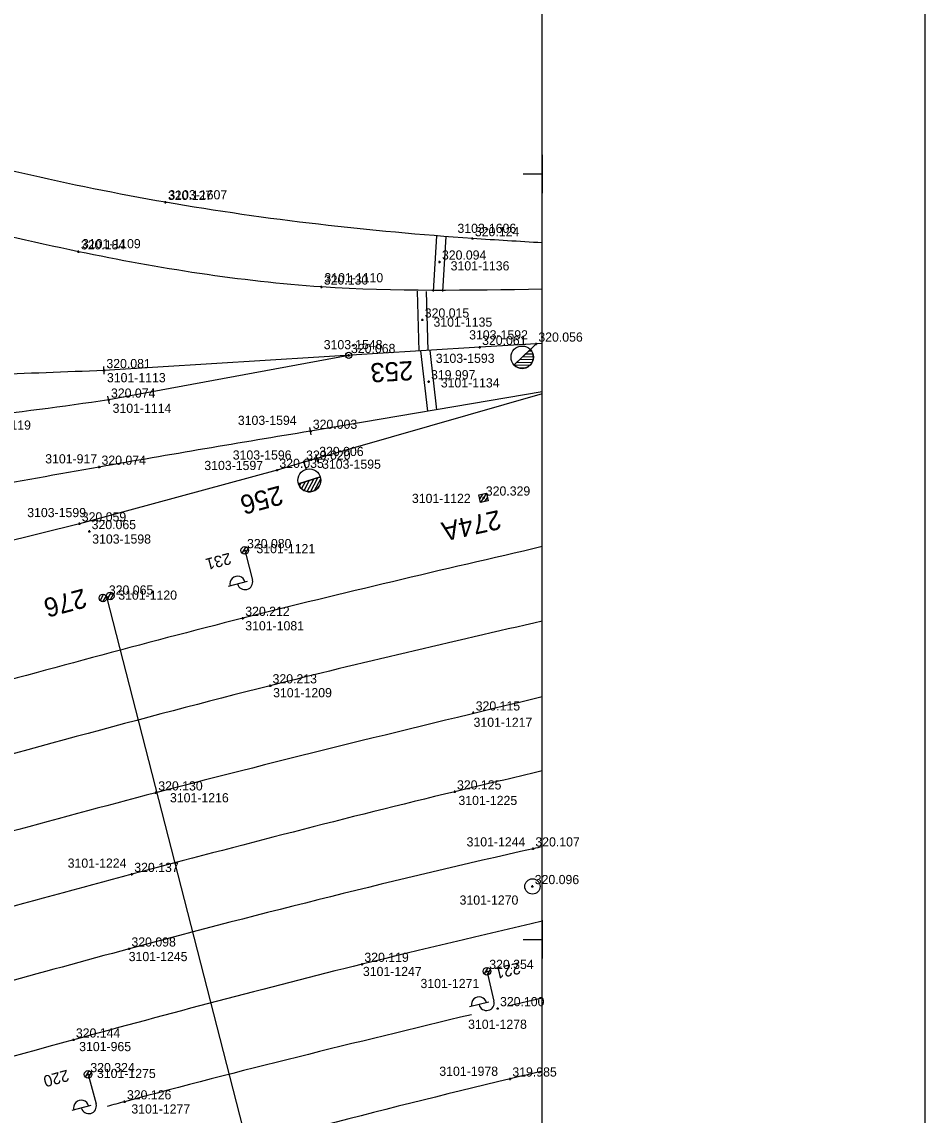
# Model space of a CAD drawing. Extents: x -821875 to -821475, y -1070280 to -1069975.
# Drawn here: x -821534 to -821475, y -1070161.5 to -1070090.1 of the extents above; entities that cross this region are included whole.
import ezdxf

# ---------------------------------------------------------------- set-up
doc = ezdxf.new("R2010")
doc.units = 0
for name, color, linetype in [('Vrstva 1', 7, 'Continuous'), ('Vrstva 11', 7, 'Continuous'), ('Vrstva 2', 7, 'Continuous'), ('Vrstva 25', 7, 'Continuous'), ('Vrstva 3', 7, 'Continuous'), ('Vrstva 43', 7, 'Continuous'), ('Vrstva 60', 7, 'Continuous'), ('Vrstva 61', 7, 'Continuous'), ('Vrstva 7', 7, 'Continuous')]:
    doc.layers.add(name, color=color, linetype=linetype)

# ---------------------------------------------------------------- blocks, each defined once
blk = doc.blocks.new('BOD')
at = {"layer": 'Vrstva 3'}
for p, q in [((-0.15, 0), (0.15, 0)), ((0, -0.15), (0, 0.15))]:
    blk.add_line(p, q, dxfattribs=at)

msp = doc.modelspace()

# ---------------------------------------------------------------- linework, layer by layer
at = {"layer": 'Vrstva 1'}
msp.add_line((-821500, -1070153.839), (-821502.241, -1070154.359), dxfattribs=at)
for points in [[(-821475, -1069975), (-821875, -1069975), (-821875, -1070275), (-821475, -1070275)], [(-821500, -1070000), (-821850, -1070000), (-821850, -1070250), (-821500, -1070250)], [(-821500, -1070000), (-821850, -1070000), (-821850, -1070250), (-821500, -1070250)]]:
    msp.add_lwpolyline(points, close=True, dxfattribs=at)
for points in [[(-821500, -1070100), (-821500, -1070098.75), (-821500, -1070100)], [(-821501.25, -1070100), (-821500, -1070100)], [(-821500, -1070100), (-821500, -1070101.25)], [(-821500, -1070111.081), (-821500.408, -1070111.107)], [(-821514.719, -1070118.578), (-821515.574, -1070118.819)], [(-821500, -1070150), (-821500, -1070148.75), (-821500, -1070150)], [(-821501.25, -1070150), (-821500, -1070150)], [(-821500, -1070150), (-821500, -1070151.25)]]:
    msp.add_lwpolyline(points, dxfattribs=at)
for points in [[(-821500, -1070107.532), (-821514.414, -1070107.377), (-821530.282, -1070105.08), (-821548.548, -1070100.3), (-821566.929, -1070093.631), (-821576.512, -1070089.417), (-821586.373, -1070084.578)], [(-821500, -1070104.505), (-821504.552, -1070104.218), (-821524.6, -1070101.851), (-821543.27, -1070097.565), (-821559.418, -1070092.193), (-821575.427, -1070085.277)], [(-821528.616, -1070112.837), (-821543.775, -1070113.227), (-821563.491, -1070112.067), (-821572.815, -1070110.801), (-821588.592, -1070107.193), (-821603.911, -1070102.306)], [(-821528.316, -1070114.765), (-821537.381, -1070115.9), (-821550.005, -1070116.34), (-821563.928, -1070115.755), (-821574.13, -1070114.598), (-821590.666, -1070111.251), (-821610.167, -1070105.183)], [(-821515.135, -1070116.801), (-821528.933, -1070119.148), (-821545.007, -1070122.191), (-821565.452, -1070126.847), (-821593.911, -1070134.524), (-821616.729, -1070140.773), (-821646.681, -1070148.977), (-821681.98, -1070158.691), (-821694.065, -1070162.076), (-821706.535, -1070165.88), (-821718.507, -1070169.937)], [(-821500, -1070124.347), (-821519.547, -1070129.021), (-821539.192, -1070134.264), (-821572.805, -1070143.407)], [(-821500, -1070129.211), (-821517.764, -1070133.43), (-821543.081, -1070140.233), (-821582.867, -1070151.05), (-821612.032, -1070158.997), (-821647.71, -1070168.745)], [(-821500, -1070134.157), (-821525.227, -1070140.424), (-821545.665, -1070145.962), (-821584.89, -1070156.649), (-821608.863, -1070163.173), (-821645.742, -1070173.228), (-821684.141, -1070183.689)], [(-821500, -1070139.002), (-821505.719, -1070140.359), (-821526.796, -1070145.75), (-821547.362, -1070151.333), (-821583.687, -1070161.245), (-821611.332, -1070168.765), (-821648.899, -1070179.006), (-821680.4, -1070187.609), (-821711.133, -1070195.974)], [(-821500, -1070143.947), (-821500.602, -1070144.082), (-821526.98, -1070150.62), (-821544.477, -1070155.432), (-821558.026, -1070159.151), (-821579.135, -1070164.951), (-821610.376, -1070173.463), (-821647.463, -1070183.595), (-821678.921, -1070192.191), (-821710.276, -1070200.761)], [(-821500, -1070148.817), (-821511.77, -1070151.622), (-821530.609, -1070156.564), (-821556.604, -1070163.701), (-821576.895, -1070169.217), (-821607.294, -1070177.525), (-821643.435, -1070187.343), (-821669.656, -1070194.488)], [(-821504.632, -1070154.921), (-821527.273, -1070160.604), (-821528.405, -1070160.911)], [(-821500, -1070158.612), (-821502.104, -1070159.113), (-821527.988, -1070165.772), (-821558.427, -1070174.094), (-821579.522, -1070179.891)]]:
    msp.add_spline(points, degree=3, dxfattribs=at)
at = {"layer": 'Vrstva 11'}
for p, q in [((-821503.904, -1070120.919), (-821504.084, -1070121.201)), ((-821503.646, -1070120.863), (-821504.026, -1070121.458)), ((-821503.589, -1070121.122), (-821503.767, -1070121.401)), ((-821528.644, -1070127.452), (-821528.881, -1070127.861)), ((-821528.488, -1070127.557), (-821528.713, -1070127.944)), ((-821528.453, -1070127.631), (-821517.074, -1070171.964)), ((-821528.158, -1070127.324), (-821528.396, -1070127.734)), ((-821528.003, -1070127.429), (-821528.227, -1070127.816))]:
    msp.add_line(p, q, dxfattribs=at)
msp.add_lwpolyline([(-821503.539, -1070121.35), (-821504.027, -1070121.458), (-821504.135, -1070120.97), (-821503.647, -1070120.862)], close=True, dxfattribs=at)
msp.add_lwpolyline([(-821503.539, -1070121.35), (-821504.027, -1070121.458), (-821504.135, -1070120.97), (-821503.647, -1070120.862), (-821503.539, -1070121.35)], dxfattribs=at)
for centre in [(-821528.695, -1070127.695), (-821528.695, -1070127.695), (-821528.211, -1070127.567), (-821528.211, -1070127.567)]:
    msp.add_circle(centre, 0.25, dxfattribs=at)
at = {"layer": 'Vrstva 2'}
for p, q in [((-821501.837, -1070112.48), (-821500.782, -1070111.467)), ((-821501.834, -1070112.478), (-821500.778, -1070111.464)), ((-821500.777, -1070111.464), (-821500.408, -1070111.107)), ((-821500.6, -1070112.149), (-821501.474, -1070112.131)), ((-821500.58, -1070111.965), (-821501.285, -1070111.95)), ((-821500.606, -1070111.779), (-821501.097, -1070111.769)), ((-821500.687, -1070111.592), (-821500.908, -1070111.588)), ((-821528.6, -1070113.087), (-821528.632, -1070112.587)), ((-821501.837, -1070112.481), (-821501.837, -1070112.48)), ((-821500.819, -1070112.514), (-821501.823, -1070112.494)), ((-821500.672, -1070112.332), (-821501.663, -1070112.312)), ((-821501.178, -1070112.692), (-821501.474, -1070112.686)), ((-821528.271, -1070115.011), (-821528.361, -1070114.519)), ((-821515.093, -1070117.048), (-821515.177, -1070116.554)), ((-821514.65, -1070118.819), (-821514.788, -1070118.337)), ((-821515.574, -1070118.819), (-821515.428, -1070119.297)), ((-821514.492, -1070119.796), (-821515.927, -1070120.234)), ((-821515.927, -1070120.234), (-821514.492, -1070119.796)), ((-821515.553, -1070120.68), (-821515.197, -1070120.011)), ((-821515.362, -1070120.747), (-821514.926, -1070119.928)), ((-821515.142, -1070120.76), (-821514.656, -1070119.846)), ((-821514.876, -1070120.686), (-821514.467, -1070119.918)), ((-821515.854, -1070120.394), (-821515.738, -1070120.176)), ((-821515.718, -1070120.564), (-821515.467, -1070120.094))]:
    msp.add_line(p, q, dxfattribs=at)
for points in [[(-821500.408, -1070111.107), (-821504.082, -1070111.324), (-821528.616, -1070112.837)], [(-821512.643, -1070111.852), (-821528.316, -1070114.765)], [(-821500, -1070114.227), (-821515.135, -1070116.801)], [(-821500, -1070114.359), (-821514.719, -1070118.578)], [(-821517.318, -1070119.351), (-821530.222, -1070122.85), (-821540.596, -1070125.428)], [(-821515.574, -1070118.819), (-821517.318, -1070119.351)]]:
    msp.add_lwpolyline(points, dxfattribs=at)
for centre, radius in [((-821501.309, -1070111.973), 0.731), ((-821512.643, -1070111.852), 0.2), ((-821515.209, -1070120.015), 0.75)]:
    msp.add_circle(centre, radius, dxfattribs=at)
for centre, radius, start, end in [((-821501.31, -1070111.974), 0.732, 223.85996, 43.82081), ((-821515.209, -1070120.015), 0.75, 196.95416, 16.95416)]:
    msp.add_arc(centre, radius, start, end, dxfattribs=at)
at = {"layer": 'Vrstva 25'}
for p, q in [((-821519.37, -1070124.354), (-821519.613, -1070124.768)), ((-821519.218, -1070124.465), (-821519.441, -1070124.845)), ((-821519.368, -1070124.838), (-821518.926, -1070126.531)), ((-821519.264, -1070126.62), (-821520.523, -1070126.948)), ((-821503.546, -1070151.845), (-821503.799, -1070152.252)), ((-821503.397, -1070151.959), (-821503.629, -1070152.333)), ((-821503.556, -1070152.329), (-821503.155, -1070154.032)), ((-821503.496, -1070154.112), (-821504.762, -1070154.41)), ((-821529.605, -1070158.583), (-821529.842, -1070158.998)), ((-821529.452, -1070158.692), (-821529.67, -1070159.073)), ((-821529.597, -1070159.066), (-821529.137, -1070160.754)), ((-821529.474, -1070160.846), (-821530.728, -1070161.189))]:
    msp.add_line(p, q, dxfattribs=at)
for centre in [(-821519.431, -1070124.596), (-821519.431, -1070124.596), (-821503.613, -1070152.085), (-821503.613, -1070152.085), (-821529.663, -1070158.825), (-821529.663, -1070158.825)]:
    msp.add_circle(centre, 0.25, dxfattribs=at)
for centre, start, end in [((-821519.895, -1070126.778), 13.92586, 195.33101), ((-821519.41, -1070126.657), 194.62844, 14.62844), ((-821504.131, -1070154.255), 12.51674, 193.92189), ((-821503.642, -1070154.146), 193.21932, 13.21932), ((-821530.103, -1070161.012), 14.56134, 195.96648), ((-821529.619, -1070160.886), 195.26391, 15.26391)]:
    msp.add_arc(centre, 0.5, start, end, dxfattribs=at)
at = {"layer": 'Vrstva 43'}
msp.add_circle((-821500.642, -1070146.543), 0.5, dxfattribs=at)
at = {"layer": 'Vrstva 7'}
for p, q in [((-821506.898, -1070104.051), (-821507.124, -1070107.68)), ((-821506.3, -1070104.097), (-821506.524, -1070107.687)), ((-821508.176, -1070107.66), (-821508.069, -1070111.57)), ((-821507.576, -1070107.672), (-821507.47, -1070111.533)), ((-821507.951, -1070111.563), (-821507.496, -1070115.502)), ((-821507.351, -1070111.526), (-821506.903, -1070115.401))]:
    msp.add_line(p, q, dxfattribs=at)

# ---------------------------------------------------------------- block references
at = {"layer": 'Vrstva 60', "xscale": 0.5, "yscale": 0.5}
for p in [(-821524.6, -1070101.851), (-821504.552, -1070104.218), (-821530.282, -1070105.08), (-821506.703, -1070105.746), (-821514.414, -1070107.377), (-821507.825, -1070109.53), (-821504.082, -1070111.324), (-821500.408, -1070111.107), (-821512.643, -1070111.852), (-821528.616, -1070112.837), (-821507.417, -1070113.568), (-821528.316, -1070114.765), (-821515.135, -1070116.801), (-821514.719, -1070118.578), (-821528.933, -1070119.148), (-821517.318, -1070119.351), (-821515.574, -1070118.819), (-821503.837, -1070121.16), (-821530.222, -1070122.85), (-821529.578, -1070123.354), (-821519.431, -1070124.596), (-821528.453, -1070127.631), (-821519.547, -1070129.021), (-821517.764, -1070133.43), (-821504.499, -1070135.2), (-821525.227, -1070140.424), (-821505.719, -1070140.359), (-821500.602, -1070144.082), (-821526.796, -1070145.75), (-821500.642, -1070146.543), (-821526.98, -1070150.62), (-821511.77, -1070151.622), (-821503.613, -1070152.085), (-821502.91, -1070154.516), (-821530.609, -1070156.564), (-821529.663, -1070158.825), (-821502.104, -1070159.113), (-821527.273, -1070160.604)]:
    msp.add_blockref('BOD', p, dxfattribs=at)

# ---------------------------------------------------------------- texts
at = {"layer": 'Vrstva 11'}
for s, rotation, p in [('274A', 192.48141, (-821502.855, -1070121.945)), ('276', 194.88708, (-821529.958, -1070127.07))]:
    msp.add_text(s, height=1.25, rotation=rotation, dxfattribs=at).set_placement(p)
at = {"layer": 'Vrstva 2'}
for s, rotation, p in [('253', 183.38017, (-821508.468, -1070112.213)), ('256', 195.1713, (-821517.135, -1070120.338))]:
    msp.add_text(s, height=1.25, rotation=rotation, dxfattribs=at).set_placement(p)
at = {"layer": 'Vrstva 25'}
for s, rotation, p in [('231', 194.62854, (-821520.428, -1070124.736)), ('221', 193.21919, (-821501.52, -1070151.492)), ('220', 195.26401, (-821531.028, -1070158.504))]:
    msp.add_text(s, height=0.75, rotation=rotation, dxfattribs=at).set_placement(p)
at = {"layer": 'Vrstva 60'}
for s, p in [('3103-1607', (-821524.414, -1070101.661)), ('3103-1606', (-821505.54, -1070103.851)), ('3101-1109', (-821530.061, -1070104.855)), ('3101-1136', (-821505.984, -1070106.303)), ('3101-1110', (-821514.228, -1070107.081)), ('3101-1135', (-821507.106, -1070109.98)), ('3103-1592', (-821504.775, -1070110.811)), ('3103-1548', (-821514.271, -1070111.45)), ('3103-1593', (-821506.956, -1070112.342)), ('3101-1113', (-821528.43, -1070113.607)), ('3101-1134', (-821506.627, -1070113.947)), ('3101-1114', (-821528.059, -1070115.606)), ('3101-1119', (-821537.231, -1070116.706)), ('3103-1594', (-821519.88, -1070116.396)), ('3101-917', (-821532.46, -1070118.909)), ('3103-1596', (-821520.213, -1070118.658)), ('3103-1597', (-821522.07, -1070119.343)), ('3103-1595', (-821514.378, -1070119.259)), ('3101-1122', (-821508.513, -1070121.495)), ('3103-1599', (-821533.634, -1070122.42)), ('3103-1598', (-821529.39, -1070124.149)), ('3101-1121', (-821518.668, -1070124.778)), ('3101-1120', (-821527.69, -1070127.813)), ('3101-1081', (-821519.397, -1070129.816)), ('3101-1209', (-821517.576, -1070134.187)), ('3101-1217', (-821504.488, -1070136.117)), ('3101-1216', (-821524.313, -1070141.05)), ('3101-1225', (-821505.476, -1070141.225)), ('3101-1244', (-821504.944, -1070143.931)), ('3101-1224', (-821530.994, -1070145.32)), ('3101-1270', (-821505.4, -1070147.733)), ('3101-1245', (-821527.007, -1070151.422)), ('3101-1247', (-821511.713, -1070152.396)), ('3101-1271', (-821507.954, -1070153.183)), ('3101-1278', (-821504.844, -1070155.845)), ('3101-965', (-821530.242, -1070157.303)), ('3101-1275', (-821529.08, -1070159.059)), ('3101-1978', (-821506.724, -1070158.915)), ('3101-1277', (-821526.834, -1070161.378))]:
    msp.add_text(s, height=0.6, dxfattribs=at).set_placement(p)
at = {"layer": 'Vrstva 61'}
for s, p in [('320.127', (-821524.45, -1070101.701)), ('320.124', (-821504.402, -1070104.068)), ('320.184', (-821530.132, -1070104.93)), ('320.094', (-821506.553, -1070105.596)), ('320.130', (-821514.264, -1070107.227)), ('320.015', (-821507.675, -1070109.38)), ('320.061', (-821503.932, -1070111.174)), ('320.056', (-821500.258, -1070110.957)), ('320.068', (-821512.493, -1070111.702)), ('320.081', (-821528.466, -1070112.687)), ('319.997', (-821507.267, -1070113.418)), ('320.074', (-821528.166, -1070114.615)), ('320.003', (-821514.985, -1070116.651)), ('320.006', (-821514.569, -1070118.428)), ('320.074', (-821528.783, -1070118.998)), ('320.035', (-821517.168, -1070119.201)), ('320.020', (-821515.424, -1070118.669)), ('320.329', (-821503.687, -1070121.01)), ('320.059', (-821530.072, -1070122.7)), ('320.065', (-821529.428, -1070123.204)), ('320.080', (-821519.281, -1070124.446)), ('320.065', (-821528.303, -1070127.481)), ('320.212', (-821519.397, -1070128.871)), ('320.213', (-821517.614, -1070133.28)), ('320.115', (-821504.349, -1070135.05)), ('320.130', (-821525.077, -1070140.274)), ('320.125', (-821505.569, -1070140.209)), ('320.107', (-821500.452, -1070143.932)), ('320.137', (-821526.646, -1070145.6)), ('320.096', (-821500.492, -1070146.393)), ('320.098', (-821526.83, -1070150.47)), ('320.119', (-821511.62, -1070151.472)), ('320.354', (-821503.463, -1070151.935)), ('320.100', (-821502.76, -1070154.366)), ('320.144', (-821530.459, -1070156.414)), ('320.324', (-821529.513, -1070158.675)), ('319.985', (-821501.954, -1070158.963)), ('320.126', (-821527.123, -1070160.454))]:
    msp.add_text(s, height=0.6, dxfattribs=at).set_placement(p)

doc.saveas('drawing.dxf')
